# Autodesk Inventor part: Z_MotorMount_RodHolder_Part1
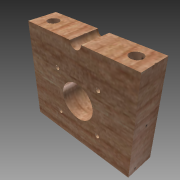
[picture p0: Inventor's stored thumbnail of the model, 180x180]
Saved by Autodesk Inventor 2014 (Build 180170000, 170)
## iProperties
Created: 2013-12
Part Number: Z_MotorMount_RodHolder_Part1
Material: Birch
Document SubType Name: Modeling
Designer: Bram
Density: 0.512 g/cm^3
Appearance: Birch - Natural Medium Gloss
Author: Bram
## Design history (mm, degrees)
sketch "Sketch1"
  geometry: L1 (-78, 0)-(-78, -66); L2 (-78, -66)-(0, -66); L3 (0, -66)-(0, 0); L4 (0, 0)-(-35, 0); L5 (-43, 0)-(-78, 0); C1 r 1.5 at (-23.5, -51.5); C2 r 1.5 at (-54.5, -51.5); C3 r 1.5 at (-23.5, -20.5); C4 r 1.5 at (-54.5, -20.5); C5 r 12 at (-39, -36); A1 r 4 centre (-39, 0) between (-43, 0) and (-35, 0)
  constraints: 10 end point, 6 centre point, 3 parallel, 2 horizontal, 2 perpendicular, 2 point on circle
  dimensions: "d0" = 78 distance of L2.end L1.end; "d1" = 66 distance of L1.end L1.start; "d7" = 3 diameter of C1; "d8" = 3 diameter of C2; "d9" = 3 diameter of C3; "d10" = 3 diameter of C4; "d12" = 24 diameter of C5; "d13" = 8 diameter of A1
extrude "Extrusion1" new body sketch "Sketch1" distance "d14" = 20; taper "d15" = 0 deg
sketch "Sketch2"
  geometry: C1 r 4 at (10, 10); C2 r 4 at (68, 10)
  constraints: 2 centre point
  dimensions: "d18" = 8 diameter of C1; "d19" = 8 diameter of C2
extrude "Extrusion2" cut sketch "Sketch2" distance "d20" = 66; taper "d21" = 0 deg
body "Solid1"
